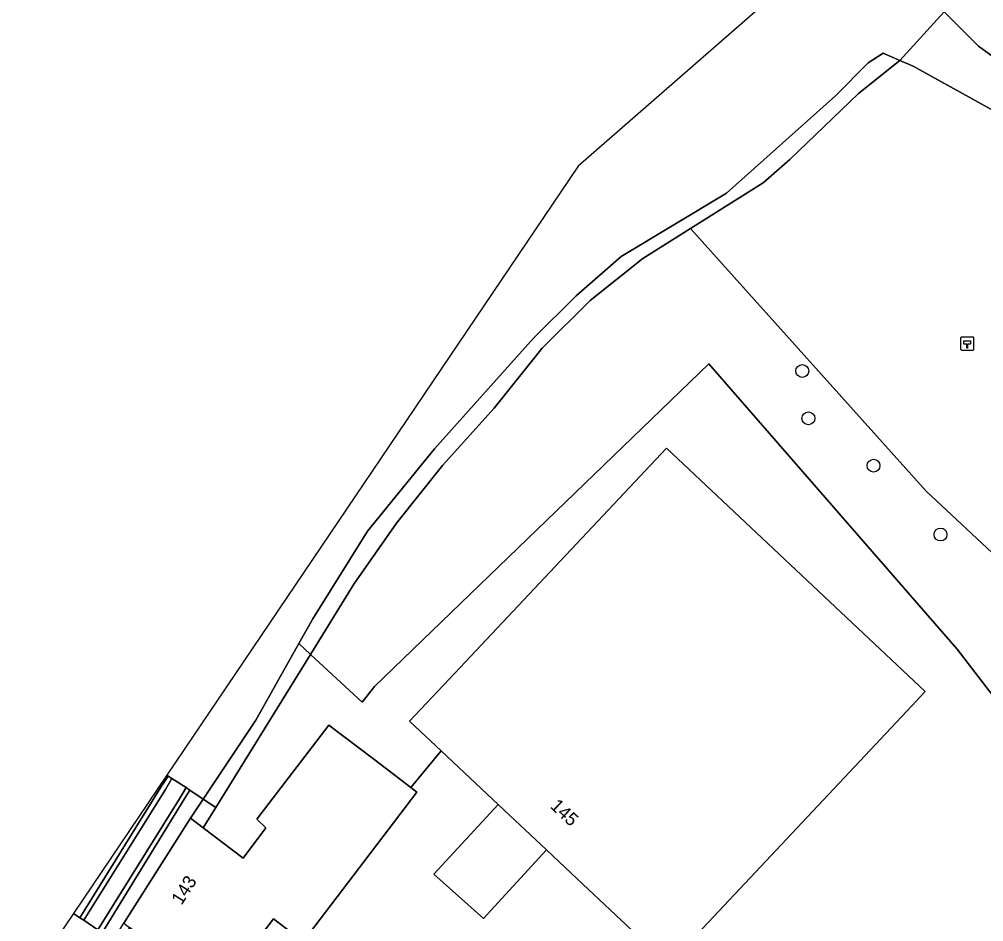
# Model space of a CAD drawing. Extents: x 160203 to 161530, y 379528 to 381797.
# Drawn here: x 160764.6 to 160837.8, y 381548.9 to 381617.4 of the extents above; entities that cross this region are included whole.
import ezdxf

# ---------------------------------------------------------------- set-up
doc = ezdxf.new("R2010")
doc.units = 0
for name, color, linetype in [('IMGEO_Boom', 7, 'Continuous'), ('IMGEO_Gemengd_bos', 7, 'Continuous'), ('IMGEO_Groenvoorziening', 7, 'Continuous'), ('IMGEO_Hectometerpaal', 7, 'Continuous'), ('IMGEO_Kademuur', 7, 'Continuous'), ('IMGEO_Loofbos', 7, 'Continuous'), ('IMGEO_Oever', 7, 'Continuous'), ('IMGEO_Pand', 7, 'Continuous'), ('IMGEO_Pand_nummerreeks', 7, 'Continuous'), ('IMGEO_Rijbaan_lokaal_open', 7, 'Continuous'), ('IMGEO_Stuw', 7, 'Continuous'), ('IMGEO_Voetpad_open', 7, 'Continuous'), ('IMGEO_Waterloop', 7, 'Continuous')]:
    doc.layers.add(name, color=color, linetype=linetype)

msp = doc.modelspace()

# ---------------------------------------------------------------- linework, layer by layer
at = {"layer": 'IMGEO_Boom'}
for centre in [(160824.04, 381590.702), (160824.508, 381587.109), (160829.457, 381583.515), (160834.545, 381578.283)]:
    msp.add_circle(centre, 0.489, dxfattribs=at)
at = {"layer": 'IMGEO_Gemengd_bos'}
msp.add_lwpolyline([(160838.477, 381576.885), (160833.453, 381581.584), (160815.552, 381601.535), (160811.921, 381599.255), (160807.917, 381596.052), (160804.287, 381592.43), (160800.621, 381587.879), (160796.713, 381583.534), (160793.202, 381579.134), (160789.981, 381574.517), (160786.68, 381569.178), (160790.594, 381565.539), (160791.534, 381566.745), (160816.943, 381591.262), (160835.809, 381569.574), (160842.52, 381560.838)], dxfattribs=at)
at = {"layer": 'IMGEO_Groenvoorziening'}
for points in [[(160843.544, 381607.742), (160832.467, 381613.869), (160831.448, 381614.306), (160828.318, 381611.794), (160823.086, 381606.764), (160821.058, 381604.992), (160815.552, 381601.535), (160833.453, 381581.584), (160838.477, 381576.885)], [(160842.52, 381560.838), (160835.809, 381569.574), (160816.943, 381591.262), (160791.534, 381566.745), (160790.594, 381565.539), (160786.68, 381569.178), (160779.482, 381557.537), (160778.531, 381555.998), (160781.553, 381553.697), (160783.297, 381556.012), (160782.59, 381556.655), (160788.064, 381563.805), (160791.479, 381561.205), (160794.298, 381559.058), (160796.596, 381561.858), (160794.207, 381564.105), (160797.633, 381567.748), (160813.719, 381584.851), (160833.386, 381566.353), (160831.977, 381564.855), (160817.3, 381549.25), (160813.874, 381545.607)]]:
    msp.add_lwpolyline(points, dxfattribs=at)
at = {"layer": 'IMGEO_Hectometerpaal'}
for p, q in [((160836.074, 381593.2), (160836.074, 381592.359)), ((160836.074, 381593.2), (160836.074, 381592.359)), ((160836.99, 381593.284), (160836.149, 381593.284)), ((160836.99, 381593.284), (160836.149, 381593.284)), ((160837.074, 381592.368), (160837.074, 381593.209)), ((160837.074, 381592.368), (160837.074, 381593.209)), ((160836.158, 381592.284), (160836.999, 381592.284)), ((160836.158, 381592.284), (160836.999, 381592.284))]:
    msp.add_line(p, q, dxfattribs=at)
msp.add_lwpolyline([(160836.599, 381592.428), (160836.539, 381592.428), (160836.539, 381592.733), (160836.319, 381592.733), (160836.319, 381593.002), (160836.819, 381593.002), (160836.819, 381592.733), (160836.599, 381592.733), (160836.599, 381592.428)], dxfattribs=at)
for centre, start, end in [((160836.152, 381593.206), 92.4484, 184.28452), ((160836.152, 381593.206), 92.4484, 184.28452), ((160836.996, 381593.206), 2.4484, 94.28452), ((160836.996, 381593.206), 2.4484, 94.28452), ((160836.152, 381592.362), 182.4484, 274.28452), ((160836.152, 381592.362), 182.4484, 274.28452), ((160836.996, 381592.362), 272.4484, 4.28452), ((160836.996, 381592.362), 272.4484, 4.28452)]:
    msp.add_arc(centre, 0.0779, start, end, dxfattribs=at)
at = {"layer": 'IMGEO_Kademuur'}
for points in [[(160775.65, 381558.908), (160776.156, 381559.736), (160775.856, 381559.935), (160775.312, 381559.081), (160769.155, 381549.174), (160769.448, 381548.975)], [(160776.998, 381558.047), (160777.515, 381558.86), (160777.241, 381559.054), (160776.723, 381558.198), (160770.524, 381548.245), (160770.852, 381548.022)]]:
    msp.add_lwpolyline(points, close=True, dxfattribs=at)
at = {"layer": 'IMGEO_Loofbos'}
msp.add_lwpolyline([(160834.812, 381617.998), (160837.429, 381615.385), (160839.089, 381614.163), (160841.128, 381613.3), (160844.566, 381611.456), (160845.506, 381610.795), (160848.887, 381609.973), (160849.867, 381609.974), (160855.662, 381611.15), (160865.78, 381614.604)], dxfattribs=at)
at = {"layer": 'IMGEO_Oever'}
for points in [[(160793.202, 381579.134), (160796.713, 381583.534), (160800.621, 381587.879), (160804.287, 381592.43), (160807.917, 381596.052), (160811.921, 381599.255), (160815.552, 381601.535), (160821.058, 381604.992), (160823.086, 381606.764), (160828.318, 381611.794), (160831.448, 381614.306), (160830.176, 381614.852), (160829.046, 381614.124), (160826.571, 381611.612), (160818.272, 381604.224), (160810.284, 381599.408), (160806.851, 381596.422), (160803.626, 381593.212), (160796.112, 381584.796), (160791.002, 381578.544), (160786.855, 381571.872), (160785.797, 381569.992), (160786.68, 381569.178), (160789.981, 381574.517)], [(160778.525, 381558.181), (160779.482, 381557.537), (160786.68, 381569.178), (160785.797, 381569.992), (160782.527, 381564.178)], [(160779.482, 381557.537), (160778.525, 381558.181), (160777.561, 381556.736), (160778.531, 381555.998)]]:
    msp.add_lwpolyline(points, close=True, dxfattribs=at)
at = {"layer": 'IMGEO_Pand'}
for points in [[(160831.977, 381564.855), (160833.386, 381566.353), (160813.719, 381584.851), (160797.633, 381567.748), (160794.207, 381564.105), (160796.596, 381561.858), (160797.957, 381560.578), (160800.945, 381557.768), (160801.405, 381557.335), (160804.605, 381554.325), (160806.951, 381552.119), (160811.112, 381548.205), (160813.874, 381545.607), (160817.3, 381549.25)], [(160794.751, 381558.713), (160794.298, 381559.058), (160791.479, 381561.205), (160788.064, 381563.805), (160782.59, 381556.655), (160783.297, 381556.012), (160781.553, 381553.697), (160778.531, 381555.998), (160777.561, 381556.736), (160772.495, 381548.762), (160772.62, 381548.667), (160772.918, 381548.44), (160779.537, 381543.401), (160783.865, 381549.085), (160786.116, 381547.371), (160789.513, 381551.833)]]:
    msp.add_lwpolyline(points, close=True, dxfattribs=at)
at = {"layer": 'IMGEO_Rijbaan_lokaal_open'}
msp.add_lwpolyline([(160811.112, 381548.205), (160806.951, 381552.119), (160804.605, 381554.325), (160799.829, 381549.12), (160796.054, 381552.486), (160800.945, 381557.768), (160797.957, 381560.578), (160796.596, 381561.858), (160794.298, 381559.058), (160794.751, 381558.713), (160789.513, 381551.833), (160786.116, 381547.371), (160783.865, 381549.085), (160779.537, 381543.401), (160772.918, 381548.44), (160771.912, 381546.776), (160778.88, 381541.228), (160775.687, 381536.434), (160779.362, 381530.937), (160783.272, 381525.087), (160788.18, 381527.659), (160785.707, 381532.573), (160805.411, 381543.37)], close=True, dxfattribs=at)
at = {"layer": 'IMGEO_Stuw'}
for points in [[(160768.677, 381549.499), (160768.677, 381549.499), (160769.155, 381549.174)], [(160769.448, 381548.975), (160770.524, 381548.245)]]:
    msp.add_lwpolyline(points, dxfattribs=at)
at = {"layer": 'IMGEO_Voetpad_open'}
msp.add_lwpolyline([(160804.605, 381554.325), (160801.405, 381557.335), (160800.945, 381557.768), (160796.054, 381552.486), (160799.829, 381549.12)], close=True, dxfattribs=at)
at = {"layer": 'IMGEO_Waterloop'}
for points in [[(160859.457, 381652.022), (160807.026, 381606.256), (160775.769, 381559.995)], [(160775.769, 381559.995), (160775.856, 381559.935), (160776.156, 381559.736), (160777.241, 381559.054), (160777.515, 381558.86), (160778.525, 381558.181), (160782.527, 381564.178), (160785.797, 381569.992), (160786.855, 381571.872), (160791.002, 381578.544), (160796.112, 381584.796), (160803.626, 381593.212), (160806.851, 381596.422), (160810.284, 381599.408), (160818.272, 381604.224), (160826.571, 381611.612), (160829.046, 381614.124), (160830.176, 381614.852), (160831.448, 381614.306), (160834.812, 381617.998)], [(160770.524, 381548.245), (160769.448, 381548.975), (160769.155, 381549.174), (160768.677, 381549.499), (160768.677, 381549.499), (160764.554, 381543.397)]]:
    msp.add_lwpolyline(points, dxfattribs=at)
for points in [[(160834.812, 381617.998), (160831.448, 381614.306), (160832.467, 381613.869), (160843.544, 381607.742), (160846.711, 381606.14), (160850.111, 381605.159), (160851.159, 381605.301), (160860.569, 381608.677), (160865.192, 381610.099), (160868.675, 381611.412), (160870.943, 381612.504), (160870.446, 381616.197), (160865.78, 381614.604), (160855.662, 381611.15), (160849.867, 381609.974), (160848.887, 381609.973), (160845.506, 381610.795), (160844.566, 381611.456), (160841.128, 381613.3), (160839.089, 381614.163), (160837.429, 381615.385)], [(160768.677, 381549.499), (160768.677, 381549.499), (160769.155, 381549.174), (160775.312, 381559.081), (160775.856, 381559.935), (160775.769, 381559.995)], [(160777.241, 381559.054), (160776.156, 381559.736), (160775.65, 381558.908), (160769.448, 381548.975), (160770.524, 381548.245), (160776.723, 381558.198)], [(160778.525, 381558.181), (160777.515, 381558.86), (160776.998, 381558.047), (160770.852, 381548.022), (160771.687, 381547.455), (160772.495, 381548.762), (160777.561, 381556.736)]]:
    msp.add_lwpolyline(points, close=True, dxfattribs=at)

# ---------------------------------------------------------------- texts
at = {"layer": 'IMGEO_Pand_nummerreeks'}
for s, rotation, p in [('145', 316.75315, (160804.828, 381557.573)), ('143', 57.5708, (160776.884, 381550.072))]:
    msp.add_text(s, height=1, rotation=rotation, dxfattribs=at).set_placement(p)

doc.saveas('drawing.dxf')
